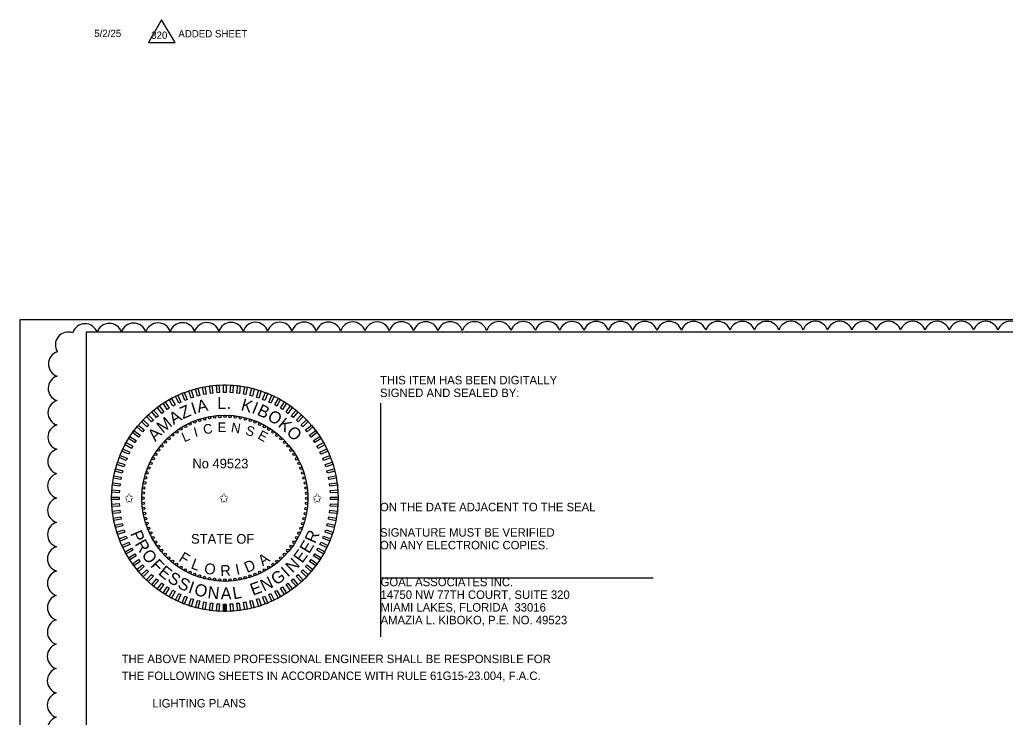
# Model space of a CAD drawing. Extents: x -811.2 to -755.6, y -2295.2 to -2235.1.
# Drawn here: x -783.91 to -775.75, y -2275.63 to -2269.86 of the extents above; entities that cross this region are included whole.
import ezdxf

# ---------------------------------------------------------------- set-up
doc = ezdxf.new("R2010")
doc.units = 0
for name, color, linetype in [('Cloud_dp', 7, 'Continuous'), ('Logo_dp', 7, 'Continuous'), ('NonPlottingEle_dp', 7, 'Continuous'), ('PlotBorder_dp', 7, 'Continuous'), ('ScratchEle_dp', 7, 'Continuous'), ('SheetBorder_dp', 7, 'Continuous'), ('TextMinor', 7, 'Continuous'), ('TextMisc', 7, 'Continuous')]:
    doc.layers.add(name, color=color, linetype=linetype)

msp = doc.modelspace()

# ---------------------------------------------------------------- linework, layer by layer
at = {"layer": 'Cloud_dp'}
msp.add_lwpolyline([(-782.7321, -2269.8629), (-782.8398, -2270.051), (-782.6192, -2270.051)], close=True, dxfattribs=at)
for centre, start, end in [((-783.3652, -2272.4837), 18.59454, 163.59454), ((-783.1638, -2272.4805), 18.21421, 163.21421), ((-782.9624, -2272.4783), 18.04696, 163.04696), ((-782.7609, -2272.4766), 17.94666, 162.94666), ((-782.5594, -2272.4751), 17.87787, 162.87787), ((-782.3579, -2272.4739), 17.82689, 162.82689), ((-782.1564, -2272.4728), 17.78716, 162.78716), ((-781.9548, -2272.4719), 17.75505, 162.75505), ((-781.7533, -2272.471), 17.72841, 162.72841), ((-781.5518, -2272.4702), 17.70584, 162.70584), ((-781.3502, -2272.4696), 17.6864, 162.6864), ((-781.1487, -2272.4689), 17.66942, 162.66942), ((-780.9472, -2272.4684), 17.65443, 162.65443), ((-780.7456, -2272.4678), 17.64106, 162.64106), ((-780.5441, -2272.4674), 17.62905, 162.62905), ((-780.3425, -2272.4669), 17.61817, 162.61817), ((-780.141, -2272.4665), 17.60826, 162.60826), ((-779.9394, -2272.4662), 17.59919, 162.59919), ((-779.7379, -2272.4658), 17.59084, 162.59084), ((-779.5364, -2272.4655), 17.58312, 162.58312), ((-779.3348, -2272.4653), 17.57595, 162.57595), ((-779.1333, -2272.465), 17.56928, 162.56928), ((-778.9317, -2272.4648), 17.56305, 162.56305), ((-778.7302, -2272.4646), 17.55721, 162.55721), ((-778.5286, -2272.4644), 17.55172, 162.55172), ((-778.3271, -2272.4642), 17.54655, 162.54655), ((-778.1255, -2272.464), 17.54167, 162.54167), ((-777.924, -2272.4639), 17.53705, 162.53705), ((-777.7224, -2272.4638), 17.53267, 162.53267), ((-777.5209, -2272.4637), 17.52851, 162.52851), ((-777.3194, -2272.4636), 17.52455, 162.52455), ((-777.1178, -2272.4635), 17.52079, 162.52079), ((-776.9163, -2272.4634), 17.51719, 162.51719), ((-776.7147, -2272.4634), 17.51375, 162.51375), ((-776.5132, -2272.4633), 17.51046, 162.51046), ((-776.3116, -2272.4633), 17.50731, 162.50731), ((-776.1101, -2272.4633), 17.50428, 162.50428), ((-775.9085, -2272.4633), 17.50138, 162.50138), ((-775.707, -2272.4633), 17.5, 162.5), ((-783.5053, -2272.5521), 68.43954, 213.43954), ((-783.563, -2272.7115), 106.80445, 251.80445), ((-783.565, -2272.9129), 107.04367, 252.04367), ((-783.5664, -2273.1144), 107.15618, 252.15618), ((-783.5675, -2273.3159), 107.22533, 252.22533), ((-783.5684, -2273.5174), 107.27338, 252.27338), ((-783.5691, -2273.719), 107.30928, 252.30928), ((-783.5697, -2273.9205), 107.33743, 252.33743), ((-783.5703, -2274.122), 107.36027, 252.36027), ((-783.5707, -2274.3236), 107.37928, 252.37928), ((-783.5711, -2274.5251), 107.39543, 252.39543), ((-783.5715, -2274.7267), 107.40937, 252.40937), ((-783.5717, -2274.9282), 107.42156, 252.42156), ((-783.572, -2275.1297), 107.43234, 252.43234), ((-783.5722, -2275.3313), 107.44197, 252.44197), ((-783.5724, -2275.5328), 107.45063, 252.45063), ((-783.5726, -2275.7344), 107.45847, 252.45847)]:
    msp.add_arc(centre, 0.1057, start, end, dxfattribs=at)
at = {"layer": 'Logo_dp'}
for p, q in [((-782.2178, -2274.759), (-782.218, -2274.6965)), ((-782.2078, -2274.759), (-782.208, -2274.6965)), ((-782.1978, -2274.759), (-782.198, -2274.6965))]:
    msp.add_line(p, q, dxfattribs=at)
for points in [[(-782.4685, -2272.9862), (-782.4877, -2272.9924), (-782.507, -2272.933), (-782.4878, -2272.9268)], [(-782.4156, -2272.9714), (-782.4351, -2272.9765), (-782.4506, -2272.916), (-782.4311, -2272.911)], [(-782.3618, -2272.9601), (-782.3816, -2272.9638), (-782.3933, -2272.9025), (-782.3735, -2272.8987)], [(-782.3074, -2272.9521), (-782.3274, -2272.9546), (-782.3352, -2272.8927), (-782.3152, -2272.8902)], [(-782.2526, -2272.9476), (-782.2727, -2272.9488), (-782.2767, -2272.8865), (-782.2565, -2272.8852)], [(-782.1976, -2272.9465), (-782.2178, -2272.9465), (-782.2178, -2272.884), (-782.1976, -2272.884)], [(-782.1427, -2272.9488), (-782.1629, -2272.9476), (-782.1589, -2272.8853), (-782.1388, -2272.8865)], [(-782.088, -2272.9547), (-782.1081, -2272.9521), (-782.1002, -2272.8902), (-782.0802, -2272.8927)], [(-782.0338, -2272.9639), (-782.0537, -2272.9601), (-782.042, -2272.8988), (-782.0221, -2272.9026)], [(-781.9803, -2272.9765), (-781.9999, -2272.9715), (-781.9844, -2272.911), (-781.9648, -2272.916)], [(-781.9277, -2272.9925), (-781.9469, -2272.9862), (-781.9276, -2272.9268), (-781.9084, -2272.9331)], [(-782.6204, -2273.0498), (-782.6381, -2273.0595), (-782.6682, -2273.0048), (-782.6505, -2272.9951)], [(-782.5712, -2273.0254), (-782.5894, -2273.034), (-782.616, -2272.9775), (-782.5978, -2272.9689)], [(-782.5205, -2273.0042), (-782.5392, -2273.0116), (-782.5622, -2272.9536), (-782.5434, -2272.9461)], [(-781.8762, -2273.0117), (-781.895, -2273.0042), (-781.872, -2272.9462), (-781.8532, -2272.9536)], [(-781.826, -2273.0341), (-781.8443, -2273.0255), (-781.8177, -2272.969), (-781.7994, -2272.9776)], [(-781.7773, -2273.0596), (-781.795, -2273.0499), (-781.7649, -2272.9952), (-781.7473, -2273.0049)], [(-782.7139, -2273.1076), (-782.7302, -2273.1195), (-782.7669, -2273.069), (-782.7506, -2273.0571)], [(-782.6681, -2273.0772), (-782.6851, -2273.0881), (-782.7186, -2273.0353), (-782.7015, -2273.0245)], [(-781.7303, -2273.0882), (-781.7474, -2273.0773), (-781.7139, -2273.0246), (-781.6969, -2273.0354)], [(-781.6852, -2273.1196), (-781.7016, -2273.1077), (-781.6649, -2273.0572), (-781.6485, -2273.0691)], [(-782.8387, -2273.2151), (-782.8525, -2273.2298), (-782.898, -2273.1871), (-782.8842, -2273.1723)], [(-782.7994, -2273.1767), (-782.8141, -2273.1905), (-782.8568, -2273.145), (-782.8421, -2273.1311)], [(-782.7577, -2273.1408), (-782.7733, -2273.1537), (-782.8131, -2273.1055), (-782.7975, -2273.0927)], [(-781.6422, -2273.1538), (-781.6578, -2273.1409), (-781.618, -2273.0928), (-781.6024, -2273.1057)], [(-781.6014, -2273.1906), (-781.6161, -2273.1768), (-781.5734, -2273.1313), (-781.5586, -2273.1451)], [(-781.563, -2273.2299), (-781.5768, -2273.2152), (-781.5313, -2273.1725), (-781.5175, -2273.1872)], [(-782.8755, -2273.2559), (-782.8884, -2273.2714), (-782.9365, -2273.2316), (-782.9237, -2273.2161)], [(-781.5271, -2273.2716), (-781.54, -2273.256), (-781.4919, -2273.2162), (-781.479, -2273.2318)], [(-782.9412, -2273.344), (-782.952, -2273.3611), (-783.0047, -2273.3276), (-782.9939, -2273.3106)], [(-782.9097, -2273.2989), (-782.9216, -2273.3153), (-782.9721, -2273.2786), (-782.9603, -2273.2622)], [(-781.4939, -2273.3154), (-781.5058, -2273.2991), (-781.4553, -2273.2624), (-781.4434, -2273.2787)], [(-781.4635, -2273.3612), (-781.4744, -2273.3442), (-781.4216, -2273.3107), (-781.4108, -2273.3278)], [(-782.9952, -2273.4397), (-783.0038, -2273.458), (-783.0603, -2273.4314), (-783.0517, -2273.4131)], [(-782.9697, -2273.391), (-782.9794, -2273.4087), (-783.0341, -2273.3786), (-783.0244, -2273.361)], [(-781.4361, -2273.4089), (-781.4458, -2273.3912), (-781.3911, -2273.3611), (-781.3814, -2273.3788)], [(-781.4117, -2273.4582), (-781.4203, -2273.4399), (-781.3638, -2273.4133), (-781.3552, -2273.4316)], [(-783.0176, -2273.4899), (-783.0251, -2273.5087), (-783.0831, -2273.4857), (-783.0757, -2273.4669)], [(-781.3905, -2273.5089), (-781.3979, -2273.4901), (-781.3399, -2273.4671), (-781.3324, -2273.4859)], [(-783.0528, -2273.594), (-783.0578, -2273.6136), (-783.1183, -2273.5981), (-783.1133, -2273.5785)], [(-783.0369, -2273.5414), (-783.0431, -2273.5606), (-783.1025, -2273.5413), (-783.0963, -2273.5221)], [(-781.3725, -2273.5608), (-781.3787, -2273.5416), (-781.3193, -2273.5223), (-781.3131, -2273.5415)], [(-781.3577, -2273.6138), (-781.3628, -2273.5942), (-781.3023, -2273.5787), (-781.2973, -2273.5982)], [(-783.0654, -2273.6475), (-783.0692, -2273.6674), (-783.1306, -2273.6557), (-783.1268, -2273.6358)], [(-781.3464, -2273.6675), (-781.3502, -2273.6477), (-781.2888, -2273.636), (-781.285, -2273.6558)], [(-783.0747, -2273.7017), (-783.0772, -2273.7218), (-783.1391, -2273.7139), (-783.1366, -2273.6939)], [(-781.3384, -2273.7219), (-781.3409, -2273.7019), (-781.279, -2273.6941), (-781.2765, -2273.7141)], [(-783.0828, -2273.8113), (-783.0828, -2273.8315), (-783.1453, -2273.8315), (-783.1453, -2273.8113)], [(-783.0805, -2273.7564), (-783.0817, -2273.7765), (-783.1441, -2273.7726), (-783.1428, -2273.7525)], [(-781.3339, -2273.7767), (-781.3351, -2273.7566), (-781.2728, -2273.7527), (-781.2716, -2273.7728)], [(-781.3328, -2273.8317), (-781.3328, -2273.8115), (-781.2703, -2273.8115), (-781.2703, -2273.8317)], [(-783.0818, -2273.8663), (-783.0805, -2273.8864), (-783.1428, -2273.8904), (-783.1441, -2273.8702)], [(-781.3351, -2273.8866), (-781.3339, -2273.8665), (-781.2716, -2273.8704), (-781.2728, -2273.8905)], [(-783.0772, -2273.9211), (-783.0747, -2273.9411), (-783.1366, -2273.9489), (-783.1392, -2273.9289)], [(-783.0693, -2273.9755), (-783.0655, -2273.9953), (-783.1268, -2274.007), (-783.1306, -2273.9872)], [(-781.3502, -2273.9955), (-781.3464, -2273.9756), (-781.2851, -2273.9873), (-781.2889, -2274.0072)], [(-781.341, -2273.9413), (-781.3384, -2273.9213), (-781.2765, -2273.9291), (-781.279, -2273.9491)], [(-783.0579, -2274.0293), (-783.0529, -2274.0488), (-783.1133, -2274.0643), (-783.1184, -2274.0448)], [(-781.3628, -2274.049), (-781.3578, -2274.0294), (-781.2973, -2274.045), (-781.3023, -2274.0645)], [(-783.0432, -2274.0822), (-783.0369, -2274.1014), (-783.0963, -2274.1207), (-783.1025, -2274.1015)], [(-783.0251, -2274.1342), (-783.0177, -2274.1529), (-783.0758, -2274.1759), (-783.0832, -2274.1571)], [(-781.398, -2274.1531), (-781.3906, -2274.1343), (-781.3325, -2274.1573), (-781.3399, -2274.1761)], [(-781.3788, -2274.1016), (-781.3725, -2274.0824), (-781.3131, -2274.1017), (-781.3194, -2274.1209)], [(-783.0039, -2274.1849), (-782.9953, -2274.2031), (-783.0518, -2274.2297), (-783.0604, -2274.2114)], [(-781.4204, -2274.2033), (-781.4118, -2274.185), (-781.3553, -2274.2116), (-781.3639, -2274.2299)], [(-782.9795, -2274.2341), (-782.9698, -2274.2518), (-783.0245, -2274.2819), (-783.0342, -2274.2642)], [(-782.9521, -2274.2818), (-782.9413, -2274.2988), (-782.994, -2274.3323), (-783.0048, -2274.3152)], [(-781.4745, -2274.299), (-781.4636, -2274.2819), (-781.4109, -2274.3154), (-781.4217, -2274.3324)], [(-781.4459, -2274.252), (-781.4362, -2274.2343), (-781.3815, -2274.2644), (-781.3912, -2274.2821)], [(-782.9217, -2274.3276), (-782.9099, -2274.3439), (-782.9604, -2274.3806), (-782.9722, -2274.3643)], [(-782.8885, -2274.3714), (-782.8757, -2274.387), (-782.9238, -2274.4268), (-782.9366, -2274.4112)], [(-781.5401, -2274.3871), (-781.5272, -2274.3716), (-781.4791, -2274.4114), (-781.492, -2274.4269)], [(-781.5059, -2274.3441), (-781.494, -2274.3277), (-781.4435, -2274.3644), (-781.4554, -2274.3808)], [(-782.8527, -2274.4131), (-782.8388, -2274.4278), (-782.8844, -2274.4705), (-782.8982, -2274.4558)], [(-782.8142, -2274.4524), (-782.7995, -2274.4662), (-782.8423, -2274.5117), (-782.857, -2274.4979)], [(-781.6162, -2274.4663), (-781.6015, -2274.4525), (-781.5588, -2274.498), (-781.5735, -2274.5119)], [(-781.5769, -2274.4279), (-781.5631, -2274.4132), (-781.5176, -2274.456), (-781.5314, -2274.4707)], [(-782.7734, -2274.4892), (-782.7579, -2274.5021), (-782.7977, -2274.5502), (-782.8132, -2274.5373)], [(-782.7304, -2274.5234), (-782.7141, -2274.5353), (-782.7508, -2274.5858), (-782.7671, -2274.5739)], [(-782.6853, -2274.5549), (-782.6682, -2274.5657), (-782.7017, -2274.6184), (-782.7187, -2274.6076)], [(-781.7475, -2274.5658), (-781.7305, -2274.555), (-781.697, -2274.6077), (-781.7141, -2274.6185)], [(-781.7017, -2274.5354), (-781.6854, -2274.5235), (-781.6487, -2274.5741), (-781.665, -2274.5859)], [(-781.6579, -2274.5022), (-781.6423, -2274.4894), (-781.6025, -2274.5375), (-781.6181, -2274.5503)], [(-782.6383, -2274.5834), (-782.6206, -2274.5931), (-782.6507, -2274.6478), (-782.6684, -2274.6381)], [(-782.5896, -2274.6089), (-782.5713, -2274.6175), (-782.5979, -2274.674), (-782.6162, -2274.6654)], [(-782.5394, -2274.6313), (-782.5206, -2274.6388), (-782.5436, -2274.6968), (-782.5624, -2274.6894)], [(-781.8952, -2274.6388), (-781.8764, -2274.6314), (-781.8534, -2274.6895), (-781.8722, -2274.6969)], [(-781.8445, -2274.6176), (-781.8262, -2274.609), (-781.7996, -2274.6655), (-781.8179, -2274.6741)], [(-781.7952, -2274.5932), (-781.7775, -2274.5835), (-781.7474, -2274.6382), (-781.7651, -2274.6479)], [(-782.4879, -2274.6506), (-782.4687, -2274.6568), (-782.488, -2274.7162), (-782.5072, -2274.7099)], [(-782.4353, -2274.6665), (-782.4157, -2274.6715), (-782.4313, -2274.732), (-782.4508, -2274.727)], [(-782.3818, -2274.6791), (-782.362, -2274.6829), (-782.3737, -2274.7442), (-782.3935, -2274.7405)], [(-782.3276, -2274.6884), (-782.3076, -2274.6909), (-782.3154, -2274.7528), (-782.3354, -2274.7503)], [(-782.2729, -2274.6942), (-782.2528, -2274.6954), (-782.2567, -2274.7578), (-782.2768, -2274.7565)], [(-782.218, -2274.6965), (-782.1978, -2274.6965), (-782.1978, -2274.759), (-782.218, -2274.759)], [(-782.163, -2274.6954), (-782.1429, -2274.6942), (-782.139, -2274.7565), (-782.1591, -2274.7578)], [(-782.1082, -2274.6909), (-782.0882, -2274.6884), (-782.0804, -2274.7503), (-782.1004, -2274.7529)], [(-782.0539, -2274.6829), (-782.034, -2274.6792), (-782.0223, -2274.7405), (-782.0422, -2274.7443)], [(-782.0001, -2274.6716), (-781.9805, -2274.6666), (-781.965, -2274.727), (-781.9845, -2274.7321)], [(-781.9471, -2274.6569), (-781.9279, -2274.6506), (-781.9086, -2274.71), (-781.9278, -2274.7162)]]:
    msp.add_lwpolyline(points, close=True, dxfattribs=at)
for centre in [(-782.4166, -2273.177), (-782.3757, -2273.1652), (-782.3342, -2273.1559), (-782.2922, -2273.1493), (-782.2498, -2273.1453), (-782.2072, -2273.144), (-782.1647, -2273.1454), (-782.1223, -2273.1495), (-782.0803, -2273.1561), (-782.0388, -2273.1655), (-781.9979, -2273.1774), (-782.5703, -2273.2492), (-782.5337, -2273.2276), (-782.4958, -2273.2083), (-782.4567, -2273.1914), (-781.9579, -2273.1918), (-781.9189, -2273.2088), (-781.8809, -2273.2281), (-781.8443, -2273.2498), (-782.6712, -2273.3273), (-782.6392, -2273.2991), (-782.6056, -2273.2731), (-781.8092, -2273.2738), (-781.7755, -2273.2999), (-781.7436, -2273.328), (-782.7556, -2273.4228), (-782.7295, -2273.3892), (-782.7013, -2273.3573), (-781.7136, -2273.3582), (-781.6855, -2273.3901), (-781.6594, -2273.4238), (-782.8012, -2273.4946), (-782.7795, -2273.458), (-781.6355, -2273.459), (-781.6139, -2273.4956), (-782.8375, -2273.5716), (-782.8206, -2273.5325), (-781.5946, -2273.5336), (-781.5777, -2273.5726), (-782.8639, -2273.6525), (-782.852, -2273.6116), (-781.5633, -2273.6127), (-781.5515, -2273.6536), (-782.8799, -2273.736), (-782.8732, -2273.694), (-781.5422, -2273.6951), (-781.5356, -2273.7372), (-782.8853, -2273.8209), (-782.8839, -2273.7784), (-781.5316, -2273.7795), (-781.5303, -2273.8221), (-782.884, -2273.8635), (-782.88, -2273.9059), (-781.5358, -2273.907), (-781.5317, -2273.8646), (-782.8734, -2273.9479), (-782.8641, -2273.9894), (-781.5518, -2273.9905), (-781.5425, -2273.949), (-782.8523, -2274.0303), (-782.8379, -2274.0704), (-781.5781, -2274.0714), (-781.5637, -2274.0314), (-782.821, -2274.1094), (-782.8018, -2274.1474), (-781.6144, -2274.1484), (-781.5951, -2274.1105), (-782.7801, -2274.184), (-782.7562, -2274.2193), (-781.6601, -2274.2202), (-781.6361, -2274.185), (-782.7302, -2274.2529), (-782.7021, -2274.2849), (-782.672, -2274.315), (-781.7445, -2274.3157), (-781.7143, -2274.2857), (-781.6862, -2274.2538), (-782.6401, -2274.3431), (-782.6065, -2274.3693), (-782.5713, -2274.3932), (-781.8453, -2274.3938), (-781.8101, -2274.3699), (-781.7764, -2274.3439), (-782.5347, -2274.4149), (-782.4968, -2274.4343), (-782.4577, -2274.4512), (-782.4177, -2274.4656), (-782.3768, -2274.4776), (-782.3353, -2274.4869), (-782.0814, -2274.4871), (-782.0399, -2274.4778), (-781.999, -2274.466), (-781.9589, -2274.4516), (-781.9199, -2274.4347), (-781.8819, -2274.4154), (-782.2933, -2274.4936), (-782.2509, -2274.4976), (-782.2078, -2274.499), (-782.1658, -2274.4977), (-782.1235, -2274.4937)]:
    msp.add_circle(centre, 0.01, dxfattribs=at)
at = {"layer": 'NonPlottingEle_dp'}
for radius in [0.9375, 0.6875]:
    msp.add_circle((-782.2078, -2273.8215), radius, dxfattribs=at)
at = {"layer": 'PlotBorder_dp'}
msp.add_lwpolyline([(-783.9062, -2282.9457), (-767.4062, -2282.9457), (-767.4062, -2272.3457), (-783.9062, -2272.3457)], close=True, dxfattribs=at)
at = {"layer": 'ScratchEle_dp'}
for p, q in [((-780.9186, -2273.0346), (-780.9186, -2274.9693)), ((-780.9186, -2274.4793), (-778.6618, -2274.4793))]:
    msp.add_line(p, q, dxfattribs=at)
at = {"layer": 'SheetBorder_dp'}
for q in [(-783.3562, -2282.8457), (-767.9562, -2272.4457)]:
    msp.add_line((-783.3562, -2272.4457), q, dxfattribs=at)

# ---------------------------------------------------------------- texts
at = {"layer": 'Cloud_dp'}
msp.add_text('320', height=0.05998, rotation=0, dxfattribs=at).set_placement((-782.8179, -2270.0208))
at = {"layer": 'Logo_dp'}
for s, rotation, p in [('I', 14.81888, (-782.4534, -2273.3163)), ('C', 8.98261, (-782.3808, -2273.2936)), ('E', 359.96623, (-782.2681, -2273.2747)), ('N', 350.64643, (-782.1612, -2273.2733)), ('S', 341.03996, (-782.0441, -2273.2921)), ('L', 23.30524, (-782.544, -2273.3592)), ('E', 331.16864, (-781.9426, -2273.3247))]:
    msp.add_text(s, height=0.08, rotation=rotation, dxfattribs=at).set_placement(p)
for p in [(-783.0428, -2273.8595), (-782.2581, -2273.8595), (-781.4862, -2273.8595)]:
    msp.add_text('✩', height=0.08, dxfattribs=at).set_placement(p)
at = {"layer": 'TextMinor'}
for s, p in [('5/2/25', (-783.2889, -2270.006)), ('ADDED SHEET', (-782.593, -2270.0084))]:
    msp.add_text(s, height=0.06, dxfattribs=at).set_placement(p)
at = {"layer": 'TextMisc'}
for s, height, p in [('THIS ITEM HAS BEEN DIGITALLY', 0.07, (-780.9235, -2272.8795)), ('SIGNED AND SEALED BY:', 0.07, (-780.9235, -2272.9845)), ('No 49523', 0.08, (-782.4768, -2273.5743)), ('ON THE DATE ADJACENT TO THE SEAL', 0.07, (-780.9235, -2273.9295)), ('SIGNATURE MUST BE VERIFIED', 0.07, (-780.9235, -2274.1395)), ('STATE OF', 0.08, (-782.4875, -2274.1977)), ('ON ANY ELECTRONIC COPIES.', 0.07, (-780.9235, -2274.2445)), ('GOAL ASSOCIATES INC.', 0.07, (-780.9186, -2274.5493)), ('14750 NW 77TH COURT, SUITE 320', 0.07, (-780.9186, -2274.6543)), ('MIAMI LAKES, FLORIDA  33016', 0.07, (-780.9186, -2274.7593)), ('AMAZIA L. KIBOKO, P.E. NO. 49523', 0.07, (-780.9186, -2274.8643)), ('THE ABOVE NAMED PROFESSIONAL ENGINEER SHALL BE RESPONSIBLE FOR ', 0.07, (-783.0626, -2275.1855)), ('THE FOLLOWING SHEETS IN ACCORDANCE WITH RULE 61G15-23.004, F.A.C.', 0.07, (-783.0626, -2275.3255)), ('LIGHTING PLANS', 0.07, (-782.8089, -2275.5525))]:
    msp.add_text(s, height=height, dxfattribs=at).set_placement(p)
for s, height, rotation, p in [('A', 0.1, 11.91844, (-782.4286, -2273.1146)), ('L', 0.1, 359.96623, (-782.2714, -2273.0842)), ('K', 0.1, 344.27273, (-782.0807, -2273.0914)), ('Z', 0.1, 23.30524, (-782.5548, -2273.1682)), ('I', 0.1, 17.68363, (-782.4679, -2273.1306)), ('.', 0.1, 353.78581, (-782.1947, -2273.0813)), ('I', 0.1, 337.77772, (-781.9921, -2273.1133)), ('B', 0.1, 334.48695, (-781.9482, -2273.1286)), ('M', 0.1, 39.30005, (-782.7212, -2273.2889)), ('A', 0.1, 31.46601, (-782.6322, -2273.2168)), ('O', 0.1, 327.82385, (-781.8635, -2273.1671)), ('K', 0.1, 321.0594, (-781.7739, -2273.2243)), ('A', 0.1, 46.80938, (-782.7835, -2273.3574)), ('O', 0.1, 314.20329, (-781.7043, -2273.2819)), ('P', 0.1, 293.19548, (-782.9935, -2274.1131)), ('R', 0.1, 65.28865, (-781.4614, -2274.2024)), ('R', 0.1, 300.25949, (-782.9566, -2274.199)), ('E', 0.1, 58.61694, (-781.5106, -2274.2864)), ('O', 0.1, 307.26617, (-782.9025, -2274.2908)), ('F', 0.09, 328.53399, (-782.5962, -2274.3368)), ('A', 0.09, 35.54629, (-781.8934, -2274.3861)), ('N', 0.1, 44.34211, (-781.6479, -2274.445)), ('E', 0.1, 53.99864, (-781.5679, -2274.3651)), ('F', 0.1, 314.20329, (-782.8291, -2274.3833)), ('E', 0.1, 321.0594, (-782.7657, -2274.4469)), ('L', 0.09, 339.48752, (-782.495, -2274.3998)), ('O', 0.09, 348.08156, (-782.3856, -2274.4404)), ('R', 0.09, 3.10738, (-782.2434, -2274.4666)), ('I', 0.09, 12.52485, (-782.1092, -2274.4575)), ('D', 0.09, 22.22228, (-782.0251, -2274.4406)), ('I', 0.1, 41.83906, (-781.6873, -2274.4792)), ('S', 0.1, 327.82385, (-782.6895, -2274.5074)), ('N', 0.1, 26.0618, (-781.8846, -2274.5954)), ('G', 0.1, 34.11362, (-781.7834, -2274.5452)), ('S', 0.1, 334.48695, (-782.6064, -2274.5588)), ('I', 0.1, 341.03996, (-782.5178, -2274.6001)), ('O', 0.1, 344.27273, (-782.4687, -2274.6177)), ('N', 0.1, 353.78581, (-782.3543, -2274.6476)), ('A', 0.1, 359.96623, (-782.242, -2274.6586)), ('L', 0.1, 8.98261, (-782.1363, -2274.6578)), ('E', 0.1, 20.51248, (-781.9761, -2274.6287))]:
    msp.add_text(s, height=height, rotation=rotation, dxfattribs=at).set_placement(p)

doc.saveas('drawing.dxf')
